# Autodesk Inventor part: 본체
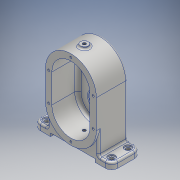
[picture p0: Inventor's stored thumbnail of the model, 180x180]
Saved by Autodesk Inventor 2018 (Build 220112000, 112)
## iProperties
Created: 2021-05
Part Number: 본체
Material: 알루미늄 6061
Document SubType Name: Modeling
Designer: admin
Density: 2.7 g/cm^3
Appearance: 알루미늄 - 평지
Author: admin
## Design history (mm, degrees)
sketch "스케치4"
  geometry: L1 (0, 0)-(0, 45); L2 (40, 0)-(40, 45); L3 (-40, 45)-(-40, 0); A1 r 40 centre (0, 0) between (-40, 0) and (40, 0); A2 r 40 centre (0, 45) between (40, 45) and (-40, 45); 1 further point
  constraints: 8 end point, 4 point on circle, 4 tangent, 2 centre point, 1 midpoint, 1 parallel, 1 vertical
  dimensions: "d13" = 45 distance of L1.start L1.end; "d14" = 80 distance between parallel lines of L3 L2
extrude "돌출4" new body sketch "스케치4" stored distance "d15" = 49; taper "d16" = 0 deg
sketch "스케치5"
  geometry: L1 (-40, 45)-(-40, 0) reference; L2 (40, 0)-(40, 45) reference; L3 (0, -65)-(0, 110) reference; L4 (-56, 0)-(56, 0) reference; L5 (0, 0)-(0, 45); L6 (30, 0)-(30, 45); L7 (-30, 45)-(-30, 0); A1 r 40 centre (0, 0) between (-40, 0) and (40, 0) reference; A2 r 40 centre (0, 45) between (40, 45) and (-40, 45) reference; A3 r 30 centre (0, 0) between (-30, 0) and (30, 0); A4 r 30 centre (0, 45) between (30, 45) and (-30, 45); 2 further points
  constraints: 8 end point, 4 point on circle, 4 tangent, 2 centre point, 1 collinear, 1 midpoint, 1 parallel
  dimensions: "d17" = 30 radius of A4
extrude "돌출5" cut sketch "스케치5" distance "d18" = 41; taper "d19" = 0 deg
sketch "스케치6"
  geometry: L1 (-40, 0)-(-40, -45) reference; L2 (40, -45)-(40, 0) reference; L3 (0, 0)-(0, -45); L4 (-26, 0)-(-26, -45); L5 (26, -45)-(26, 0); A1 r 40 centre (0, -45) between (-40, -45) and (40, -45) reference; A2 r 40 centre (0, 0) between (40, 0) and (-40, 0) reference; A3 r 26 centre (0, 0) between (26, 0) and (-26, 0); A4 r 26 centre (0, -45) between (-26, -45) and (26, -45); 2 further points
  constraints: 8 end point, 4 point on circle, 4 tangent, 2 centre point, 1 midpoint, 1 parallel, 1 vertical
  dimensions: "d20" = 52 distance between parallel lines of L4 L5
extrude "돌출6" join sketch "스케치6" distance "d21" = 11; taper "d22" = 0 deg
node "작업 평면1"
sketch "스케치7"
  geometry: L1 (-61, 24.5)-(61, 24.5); L2 (61, 24.5)-(61, -21.5); L3 (61, -21.5)-(-61, -21.5); L4 (-61, -21.5)-(-61, 24.5); L5 (-61, 24.5)-(61, -21.5); L6 (61, 24.5)-(-61, -21.5); L7 (0, -42.635)-(0, 84.311) reference; L8 (-85.4, 0)-(85.4, 0) reference; 4 further points
  constraints: 12 end point, 3 midpoint, 2 parallel, 2 point on line, 1 horizontal, 1 perpendicular
  dimensions: "d24" = 122 distance of L1.start L1.end; "d25" = 46 distance of L1.end L2.end
extrude "돌출7" join sketch "스케치7" distance "d26" = 10; taper "d27" = 0 deg
sketch "스케치8"
  geometry: L1 (-40, 0)-(-40, -45) reference; L2 (40, -45)-(40, 0) reference; L3 (61, 37)-(15.199, 37) reference; L4 (61, 47)-(61, 37) reference; L5 (-61, 47)-(61, 47) reference; L6 (-61, 47)-(-61, 37) reference; L7 (-15.199, 37)-(-61, 37) reference; L8 (26, 0)-(26, -45) reference; L9 (-26, -45)-(-26, 0) reference; L10 (0, 73.4)-(0, -111.4) reference; L11 (-85.4, 0)-(85.4, 0) reference; L12 (40, 0)-(40, 37); L13 (-40, 0)-(-40, 37); L14 (-15.199, 37)-(-61, 37) reference; L15 (40, 37)-(15.199, 37); L16 (-15.199, 37)-(-40, 37); A1 r 40 centre (0, 0) between (-15.199, 37) and (-40, 0) reference; A2 r 40 centre (0, -45) between (-40, -45) and (40, -45) reference; A3 r 40 centre (0, 0) between (40, 0) and (15.199, 37) reference; A4 r 26 centre (0, 0) between (26, 0) and (-26, 0) reference; A5 r 26 centre (0, -45) between (-26, -45) and (26, -45) reference; 1 further point
  constraints: 8 end point, 2 perpendicular, 2 point on line, 1 collinear
extrude "돌출8" join sketch "스케치8" stored distance "d28" = 10; taper "d29" = 0 deg
sketch "스케치9"
  geometry: L1 (61, -26.4)-(61, 158.4) reference; L2 (-24.4, 47)-(146.4, 47) reference; L3 (21, 10)-(21, 47) reference; L4 (0, 10)-(21, 10) reference; L5 (0, 0)-(0, 10) reference; L6 (122, 0)-(0, 0) reference; L7 (122, 0)-(122, 10) reference; L8 (101, 10)-(122, 10) reference; L9 (101, 47)-(101, 10) reference; L10 (26, 0)-(96, 0); L11 (96, 0)-(96, 5); L12 (96, 5)-(26, 5); L13 (26, 5)-(26, 0); L14 (26, 0)-(96, 5); L15 (96, 0)-(26, 5); L16 (122, 0)-(0, 0) reference; A1 r 40 centre (61, 47) between (21, 47) and (101, 47) reference; 2 further points
  constraints: 12 end point, 2 midpoint, 2 parallel, 2 point on line, 1 horizontal, 1 perpendicular
  dimensions: "d30" = 70 distance of L12.end L11.end; "d31" = 5 distance of L11.end L10.end
extrude "돌출9" cut sketch "스케치9" stored distance "d32" = 10; taper "d33" = 0 deg
fillet "모깎기1" dims "d34" = 10
sketch "스케치10"
  geometry: L1 (-51, 24.5)-(-35, 24.5) reference; L2 (-35, 24.5)-(-35, -21.5) reference; L3 (-35, -21.5)-(-51, -21.5) reference; L4 (-61, -11.5)-(-61, 14.5) reference; L5 (61, 14.5)-(61, -11.5) reference; L6 (51, -21.5)-(35, -21.5) reference; L7 (35, -21.5)-(35, 24.5) reference; L8 (35, 24.5)-(51, 24.5) reference; L9 (-88.299, 0)-(88.299, 0) reference; L10 (0, -36.5)-(0, 47.5) reference; A1 r 10 centre (-51, 14.5) between (-51, 24.5) and (-61, 14.5) reference; A2 r 10 centre (-51, -11.5) between (-61, -11.5) and (-51, -21.5) reference; A3 r 10 centre (51, 14.5) between (61, 14.5) and (51, 24.5) reference; A4 r 10 centre (51, -11.5) between (51, -21.5) and (61, -11.5) reference; 5 further points
  constraints: 4 coincident
hole "구멍1" sketch "스케치10" at (-51, -11.5), (-51, 14.5), (51, 14.5), (51, -11.5) diameter "d35" = 6.6; stored, may be unused: countersink angle "d39" = 90 deg, drill point angle "d41" = 118 deg; dims "d36" = 6, "d37" = 11, "d38" = 2, "d40" = 8
sketch "스케치11"
  geometry: L1 (-26, 0)-(-26, -45) reference; L2 (26, -45)-(26, 0) reference; L3 (-85.4, 0)-(85.4, 0) reference; L4 (0, 73.4)-(0, -111.4) reference; L5 (26, -15)-(-26, -15); L6 (26, -15)-(26, -45); L7 (-26, -45)-(-26, 0) reference; L8 (-26, -15)-(-26, -45); A1 r 26 centre (0, -45) between (-26, -45) and (26, -45) reference; A2 r 26 centre (0, 0) between (26, 0) and (-26, 0) reference; A3 r 26 centre (0, -45) between (-26, -45) and (26, -45) reference; 2 further points
  constraints: 6 end point, 2 point on line, 1 coincident, 1 collinear, 1 horizontal, 1 horizontal alignment, 3 other
  dimensions: "d42" = 30 distance from line of L5 A1.centre
extrude "돌출10" cut sketch "스케치11" distance "d43" = 3; taper "d44" = 0 deg
sketch "스케치12"
  geometry: L1 (16.5, 45)-(16.5, 0) reference; L2 (16.5, 45)-(16.5, 45) reference; L3 (16.5, 0)-(16.5, 45) reference; L4 (16.5, 0)-(16.5, 0) reference; L5 (0, -73.4)-(0, 111.4) reference; L6 (-36.5, 0)-(47.5, 0) reference; L7 (-43.665, 45)-(58.067, 45); L8 (16.5, 59)-(24.5, 59); L9 (24.5, 59)-(24.5, 56); L10 (24.5, 56)-(28.5, 56); L11 (28.5, 56)-(28.5, 59); L12 (28.5, 59)-(32.5, 59); L13 (32.5, 71)-(32.5, 45) reference; L14 (16.5, 45)-(16.5, 75) reference; L15 (24.5, 45)-(32.5, 45) reference; L16 (16.5, 45)-(32.5, 45); 1 further point
  constraints: 14 end point, 4 perpendicular, 3 horizontal, 3 point on line
  dimensions: "d47" = 8 distance of L8.start L8.end; "d48" = 4 distance of L11.end L12.end; "d49" = 28 diameter of L8 L7; "d50" = 28 diameter of L12 L7; "d51" = 22 diameter of L10 L7
revolve "회전1" sketch "스케치12" stored, may be unused: angle "d52" = 90 deg
sketch "스케치13"
  geometry: L1 (30, 45)-(30, 0) reference; L2 (-30, 0)-(-30, 45) reference; C1 r 14 at (0, 45) reference; C2 r 14 at (0, 0); A1 r 30 centre (0, 45) between (30, 45) and (-30, 45) reference; A2 r 30 centre (0, 0) between (-30, 0) and (30, 0) reference; 1 further point
  constraints: 1 centre point, 1 coincident
  dimensions: "d53" = 28 diameter of C2
extrude "돌출11" cut sketch "스케치13" distance "d54" = 8; taper "d55" = 0 deg
sketch "스케치14"
  geometry: C1 r 10 at (0, 0); 1 further point
  constraints: 1 centre point, 1 coincident
  dimensions: "d56" = 20 diameter of C1
extrude "돌출12" cut sketch "스케치14" distance "d57" = 4; taper "d58" = 0 deg
sketch "스케치15"
  geometry: L1 (30, 45)-(30, 0) reference; L2 (-30, 0)-(-30, 45) reference; L3 (-40, 45)-(-40, 0) reference; L4 (40, 0)-(40, 45) reference; L5 (0, -73.4)-(0, 111.4) reference; L6 (-85.4, 0)-(85.4, 0) reference; L7 (0, 45)-(0, 0); L8 (-35, 45)-(-35, 0); L9 (35, 0)-(35, 45); L10 (-82.081, 22.5)-(84.009, 22.5); A1 r 30 centre (0, 45) between (30, 45) and (-30, 45) reference; A2 r 30 centre (0, 0) between (-30, 0) and (30, 0) reference; A3 r 40 centre (0, 0) between (-40, 0) and (40, 0) reference; A4 r 40 centre (0, 45) between (40, 45) and (-40, 45) reference; A5 r 35 centre (0, 45) between (35, 45) and (-35, 45); A6 r 35 centre (0, 0) between (-35, 0) and (35, 0); 8 further points
  constraints: 10 end point, 5 point on circle, 4 tangent, 3 symmetric about line, 2 centre point, 2 coincident, 1 collinear, 1 horizontal, 1 midpoint, 1 parallel, 1 point on line
  dimensions: "d59" = 35 radius of A5
hole "구멍2" sketch "스케치15" at (-35, 0), (0, -35), (35, 0), (-35, 45), (0, 80), (35, 45) diameter "d60" = 3.242; stored, may be unused: countersink angle "d64" = 90 deg, drill point angle "d66" = 118 deg; dims "d61" = 8, "d62" = 11, "d63" = 2, "d65" = 10
sketch "스케치16" dims "d67" = 40
  geometry: L1 (0, 73.4)-(0, -111.4) reference; L2 (-85.4, 0)-(85.4, 0) reference; C1 r 11 at (0, -45) reference; 5 further points
  constraints: 1 coincident, 1 point on line, 1 vertical alignment, 6 other
  dimensions: "d70" = 360 deg dimension on point (0, -45) point (0, -65) (derived)
hole "구멍3" sketch "스케치16" at (0, -65), (17.321, -35), (-17.321, -35) diameter "d72" = 3.242; stored, may be unused: countersink angle "d76" = 90 deg, drill point angle "d78" = 118 deg; dims "d73" = 8, "d74" = 11, "d75" = 2, "d77" = 10
node "작업 평면2"
sketch "스케치17"
  geometry: L1 (0, -36.5)-(0, 47.5) reference; L2 (-85.4, 0)-(85.4, 0) reference; L3 (-40, -24.5)-(40, -24.5) reference; C1 r 6 at (0, -3.5); 1 further point
  constraints: 1 centre point, 1 point on line
  dimensions: "d80" = 12 diameter of C1; "d81" = 21 distance from line of L3 C1.centre
extrude "돌출13" join sketch "스케치17" stored distance "d82" = 4; taper "d83" = 0 deg
sketch "스케치18"
  geometry: C1 r 6 at (0, 0) reference; 2 further points
  constraints: 1 coincident
hole "구멍4" sketch "스케치18" at (0, 0) diameter "d84" = 4.917; stored, may be unused: countersink angle "d88" = 90 deg, drill point angle "d90" = 118 deg; dims "d85" = 30, "d86" = 11, "d87" = 2, "d89" = 30
fillet "모깎기2" dims "d91" = 3
sketch "스케치19"
  geometry: L1 (35, -15)-(35, 69) reference; L2 (120.4, 21.5)-(-50.4, 21.5) reference; L3 (-5, -3)-(75, -3) reference; 2 further points
  constraints: 1 point on line
  dimensions: "d92" = 21 distance from line of point (35, 18) L3
hole "구멍5" sketch "스케치19" at (35, 18) diameter "d93" = 4.917; stored, may be unused: countersink angle "d97" = 90 deg, drill point angle "d99" = 118 deg; dims "d94" = 30, "d95" = 11, "d96" = 2, "d98" = 30
sketch "스케치20"
  geometry: C1 r 2.458 at (35, 18) reference; C2 r 6 at (35, 18); 1 further point
  constraints: 1 centre point, 1 coincident
  dimensions: "d100" = 12 diameter of C2
extrude "돌출14" cut sketch "스케치20" distance "d101" = 1; taper "d102" = 0 deg
fillet "모깎기3" dims "d103" = 5
fillet "모깎기4" dims "d104" = 0.3
chamfer "모따기1" distance "d105" = 1; stored, may be unused: second distance "d106" = 2, angle "d107" = 45 deg
fillet "모깎기5" dims "d108" = 3
sketch "스케치21"
  geometry: L1 (0, 74.006)-(0, -115.034) reference; L2 (-85.4, 0)-(85.4, 0) reference; L3 (35, 47)-(51, 47) reference; 2 further points
  constraints: 1 point on line, 1 other
  dimensions: "d109" = 12 distance from line of L3 point (0, 35)
feature "엠보싱1" sketch "스케치21" dims "d13" = 45, "d14" = 80, "d110" = 0.5, "d111" = 0
node "솔리드2"
node "투영된 루프2"
node "투영된 루프3"
node "투영된 루프4"
node "투영된 루프5"
node "투영된 루프6"
node "투영된 루프7"
node "투영된 루프8"
node "투영된 루프9"
node "투영된 루프10"
node "투영된 루프11"
node "투영된 루프12"
other parameters: "d23" = -47, "d79" = 88
